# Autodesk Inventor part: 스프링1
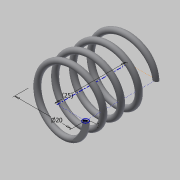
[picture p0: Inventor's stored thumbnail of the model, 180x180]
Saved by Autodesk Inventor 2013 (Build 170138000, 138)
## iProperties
Created: 2016-07
Part Number: 스프링1
Material: 일반
Document SubType Name: Modeling
Designer: dgall
Density: 1 g/cm^3
Author: dgall
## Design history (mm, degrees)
sketch "스케치1"
  geometry: L1 (0, 0)-(10, 0); L2 (10, 0)-(10, 19.5); L3 (10, 19.5)-(0, 19.5); L4 (0, 19.5)-(0, 0); C1 r 1 at (10, 0)
  constraints: 8 end point, 2 parallel, 1 centre point, 1 coincident, 1 horizontal, 1 perpendicular
  dimensions: "d0" = 2 diameter of C1; "d2" = 19.5 distance of L3.end L1.start (derived); "d3" = 20 diameter of L2 L4
feature "코일1" sketch "스케치1" pitch "d4" = 10; turns "d6" = 4; dims "d5" = 19.5 (= d2), "d7" = 0, angle "d8" = 90 deg, angle "d9" = 90 deg, "d10" = 0, "d11" = 0
feature "분할1"
node "작업 평면1"
feature "분할2"
node "솔리드1"
